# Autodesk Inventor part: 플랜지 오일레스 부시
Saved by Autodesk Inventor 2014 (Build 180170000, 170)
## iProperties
Created: 2026-03
Part Number: 플랜지 오일레스 부시
Material: 일반
Document SubType Name: Modeling
Designer: dg
Density: 1 g/cm^3
Appearance: 기본값
Author: dg
Author: jhkim
Creation Date: 2025-06-27
Sending System: Autodesk Inventor 2026
Preprocessor: ST-DEVELOPER v20.1
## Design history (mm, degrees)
node "플랜지 오일레스 부시1"
node "솔리드1"
node "기준1"
